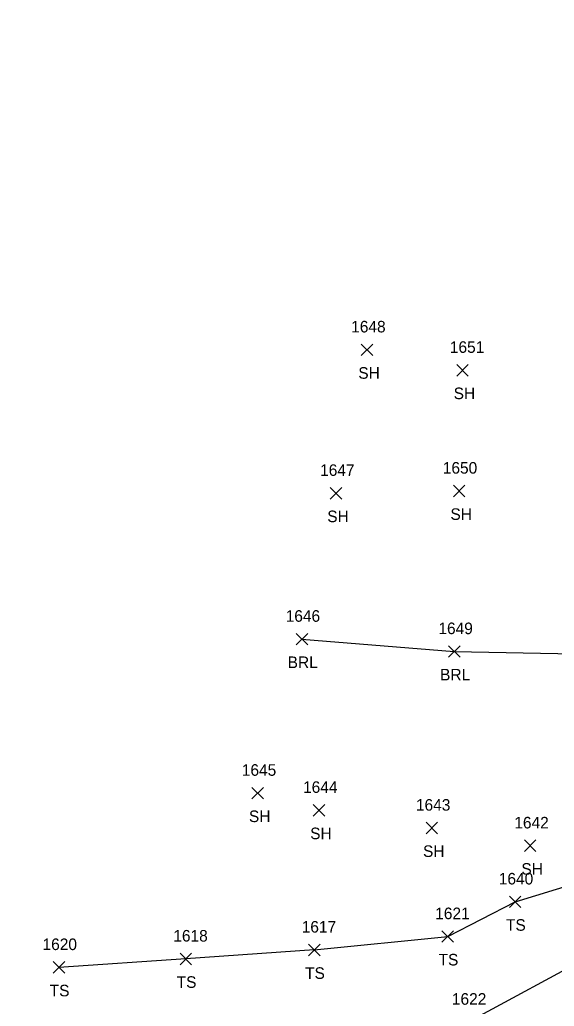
# Model space of a CAD drawing. Extents: x 1554917 to 1555870, y 813367 to 816333.
# Drawn here: x 1555121.8 to 1555214.2, y 814161.6 to 814332.2 of the extents above; entities that cross this region are included whole.
import ezdxf

# ---------------------------------------------------------------- set-up
doc = ezdxf.new("R2010")
doc.units = 0
for name, color, linetype in [('L_A', 7, 'Continuous'), ('L_I', 7, 'Continuous'), ('L_TIC', 7, 'Continuous'), ('LABL', 7, 'Continuous'), ('LELB', 7, 'Continuous')]:
    doc.layers.add(name, color=color, linetype=linetype)

msp = doc.modelspace()

# ---------------------------------------------------------------- linework, layer by layer
at = {"layer": 'L_TIC'}
for points in [[(1555180.82, 814274.09), (1555182.82, 814276.09)], [(1555182.82, 814274.09), (1555180.82, 814276.09)], [(1555197.31, 814270.56), (1555199.31, 814272.56)], [(1555199.31, 814270.56), (1555197.31, 814272.56)], [(1555175.45, 814249.29), (1555177.45, 814251.29)], [(1555177.45, 814249.29), (1555175.45, 814251.29)], [(1555196.74, 814249.68), (1555198.74, 814251.68)], [(1555198.74, 814249.68), (1555196.74, 814251.68)], [(1555169.56, 814224.07), (1555171.56, 814226.07)], [(1555171.56, 814224.07), (1555169.56, 814226.07)], [(1555195.9, 814221.93), (1555197.9, 814223.93)], [(1555197.9, 814221.93), (1555195.9, 814223.93)], [(1555161.92, 814197.44), (1555163.92, 814199.44)], [(1555163.92, 814197.44), (1555161.92, 814199.44)], [(1555172.5, 814194.48), (1555174.5, 814196.48)], [(1555174.5, 814194.48), (1555172.5, 814196.48)], [(1555192.01, 814191.41), (1555194.01, 814193.41)], [(1555194.01, 814191.41), (1555192.01, 814193.41)], [(1555209.01, 814188.34), (1555211.01, 814190.34)], [(1555211.01, 814188.34), (1555209.01, 814190.34)], [(1555206.42, 814178.65), (1555208.42, 814180.65)], [(1555208.42, 814178.65), (1555206.42, 814180.65)], [(1555194.77, 814172.65), (1555196.77, 814174.65)], [(1555196.77, 814172.65), (1555194.77, 814174.65)], [(1555171.7, 814170.33), (1555173.7, 814172.33)], [(1555173.7, 814170.33), (1555171.7, 814172.33)], [(1555171.7, 814170.33), (1555173.7, 814172.33)], [(1555173.7, 814170.33), (1555171.7, 814172.33)], [(1555149.51, 814168.78), (1555151.51, 814170.78)], [(1555151.51, 814168.78), (1555149.51, 814170.78)], [(1555127.57, 814167.31), (1555129.57, 814169.31)], [(1555129.57, 814167.31), (1555127.57, 814169.31)]]:
    msp.add_lwpolyline(points, dxfattribs=at)
at = {"layer": 'LABL'}
msp.add_lwpolyline([(1555170.56, 814225.07), (1555196.9, 814222.93), (1555217.8, 814222.5), (1555221.03, 814223.42), (1555235.64, 814238.62), (1555246.25, 814257.84), (1555251.52, 814288.71), (1555259.39, 814330.22), (1555249.41, 814332.16)], dxfattribs=at)
at = {"layer": 'LELB'}
for points in [[(1555172.7, 814171.33), (1555195.77, 814173.65), (1555207.42, 814179.65), (1555224.53, 814184.88)], [(1555103.83, 814081.29), (1555127.34, 814087.63), (1555145.8, 814111.67), (1555155.27, 814142.44), (1555178.24, 814154.02), (1555199.22, 814158.86), (1555221.17, 814170.73)], [(1555172.7, 814171.33), (1555150.51, 814169.78), (1555128.57, 814168.31)]]:
    msp.add_lwpolyline(points, dxfattribs=at)

# ---------------------------------------------------------------- texts
at = {"layer": 'L_A'}
for s, p in [('SH', (1555180.31, 814270.09)), ('SH', (1555196.79, 814266.56)), ('SH', (1555174.94, 814245.29)), ('SH', (1555196.23, 814245.68)), ('BRL', (1555168.1, 814220.07)), ('BRL', (1555194.44, 814217.93)), ('SH', (1555161.41, 814193.44)), ('SH', (1555171.99, 814190.48)), ('SH', (1555191.49, 814187.41)), ('SH', (1555208.49, 814184.34)), ('TS', (1555205.83, 814174.65)), ('TS', (1555194.18, 814168.65)), ('TS', (1555171.11, 814166.33)), ('TS', (1555171.11, 814166.33)), ('TS', (1555148.92, 814164.78)), ('TS', (1555126.98, 814163.31))]:
    msp.add_text(s, height=2, dxfattribs=at).set_placement(p)
at = {"layer": 'L_I'}
for s, p in [('1648', (1555179.08, 814278.09)), ('1651', (1555196.13, 814274.56)), ('1647', (1555173.71, 814253.29)), ('1650', (1555194.91, 814253.68)), ('1646', (1555167.76, 814228.07)), ('1649', (1555194.15, 814225.93)), ('1645', (1555160.18, 814201.44)), ('1644', (1555170.76, 814198.48)), ('1643', (1555190.27, 814195.41)), ('1642', (1555207.27, 814192.34)), ('1640', (1555204.59, 814182.65)), ('1621', (1555193.6, 814176.65)), ('1617', (1555170.53, 814174.33)), ('1617', (1555170.53, 814174.33)), ('1618', (1555148.34, 814172.78)), ('1620', (1555125.74, 814171.31)), ('1622', (1555196.48, 814161.86))]:
    msp.add_text(s, height=2, dxfattribs=at).set_placement(p)

doc.saveas('drawing.dxf')
